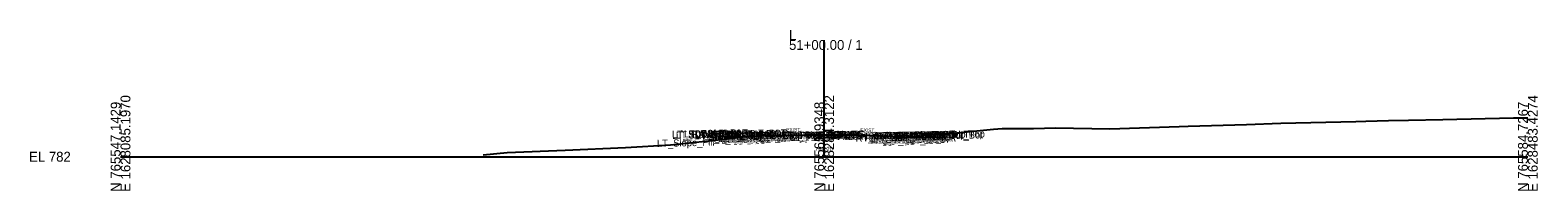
# Model space of a CAD drawing. Extents: x -26 to 4403, y -510 to 9556.
# Drawn here: x 3974.3 to 4402.8, y 990.3 to 1035.9 of the extents above; entities that cross this region are included whole.
import ezdxf

# ---------------------------------------------------------------- set-up
doc = ezdxf.new("R2010")
doc.units = 0
for name, color, linetype in [('Default', 7, 'Continuous'), ('Exist Cross Section Cell', 7, 'Continuous'), ('Exist XS Center Line Elevation Label', 7, 'Continuous'), ('Exist XS Ground Line', 7, 'Continuous'), ('Prop CMT Pvmt Course 1', 7, 'Continuous'), ('Prop XS SE Text', 7, 'Continuous'), ('Scratch_Level_0', 7, 'Continuous')]:
    doc.layers.add(name, color=color, linetype=linetype)

msp = doc.modelspace()

# ---------------------------------------------------------------- linework, layer by layer
at = {"layer": 'Exist Cross Section Cell'}
for p, q in [((4200, 1000), (4200, 1033.14)), ((4000, 1000), (4200, 1000)), ((4200, 1000), (4400, 1000))]:
    msp.add_line(p, q, dxfattribs=at)
at = {"layer": 'Exist XS Ground Line'}
msp.add_lwpolyline([(4103.02, 1000.53), (4109.92, 1001.15), (4126.34, 1001.82), (4143.53, 1002.6), (4156.34, 1003.41), (4170.67, 1004.87), (4175.04, 1005.42), (4178.52, 1005.83), (4178.89, 1005.78), (4181.08, 1005.93), (4182.4, 1005.99), (4185.35, 1006.05), (4195.01, 1006.21), (4200, 1006.2), (4204.25, 1006.19), (4207.07, 1006.19), (4216.25, 1005.9), (4219.03, 1005.8), (4220.54, 1005.71), (4225.42, 1005.51), (4226.33, 1005.6), (4227.42, 1005.73), (4227.92, 1006.09), (4229.72, 1006.21), (4231.23, 1006.3), (4234.93, 1006.51), (4248.08, 1007.84), (4250.54, 1008), (4259.47, 1007.99), (4265.74, 1008.23), (4281.22, 1007.92), (4300.92, 1008.6), (4303.46, 1008.65), (4320.01, 1009.13), (4329.77, 1009.51), (4351.1, 1010.04), (4353.96, 1010.09), (4360.43, 1010.31), (4366.12, 1010.38), (4375.84, 1010.57), (4395.9, 1011), (4400, 1011.05)], dxfattribs=at)
at = {"layer": 'Prop CMT Pvmt Course 1'}
for points in [[(4200, 1006.01), (4200, 1006.26)], [(4200, 1006.01), (4200, 1006.26)], [(4200, 1006.13), (4200, 1006.01), (4200, 1006.01)], [(4200, 1006.13), (4200, 1006.01), (4200, 1006.01)]]:
    msp.add_lwpolyline(points, dxfattribs=at)

# ---------------------------------------------------------------- texts
at = {"layer": 'Default'}
msp.add_text('-', height=0.0001, dxfattribs=at).set_placement((4000, 1000))
at = {"layer": 'Exist Cross Section Cell'}
for s, p in [('51+00.00 / 1', (4190, 1030.34)), ('L', (4190, 1033.14)), ('EL 782', (3974, 998.6))]:
    msp.add_text(s, height=2.8, dxfattribs=at).set_placement(p)
for s, p in [('E 1628085.1970', (4002.8, 990)), ('E 1628284.3122', (4202.8, 990)), ('E 1628483.4274', (4402.8, 990)), ('N 765547.1429', (4000, 990)), ('N 765565.9348', (4200, 990)), ('N 765584.7267', (4400, 990))]:
    msp.add_text(s, height=2.8, rotation=90, dxfattribs=at).set_placement(p)
at = {"layer": 'Exist XS Center Line Elevation Label'}
msp.add_text('788.20', height=1.2, dxfattribs=at).set_placement((4197.42, 1001.6))
at = {"layer": 'Prop XS SE Text'}
for rotation, p in [(0.5729, (4189.22, 1007.15)), (358.8542, (4210.27, 1007.05))]:
    msp.add_text('EXIST.', height=1, rotation=rotation, dxfattribs=at).set_placement(p)
at = {"layer": 'Scratch_Level_0'}
for s, p in [('LT_SDWK_Out_Top', (4156.76, 1005.39)), ('LT_SDWK_Out_Bot', (4156.79, 1005.06)), ('LT_Sub_Trench_Out_DLT', (4157.86, 1005.14)), ('LT_CSLP_Pnt', (4160.2, 1005.47)), ('LT_SDWK_In_Top', (4163.38, 1005.33)), ('LT_SDWK_In_Bot', (4163.41, 1005)), ('51+00.00', (4165.28, 1005.52)), ('LT_PV_Sub_Tie_Out', (4166.98, 1004.67)), ('LT_CG_Top_Face', (4167.28, 1005.23)), ('LT_CG_Top_BOC', (4167.8, 1005.25)), ('LT_CG_Top_Gut', (4168.26, 1004.74)), ('LT_PV_OEEOP_EG', (4169.57, 1004.73)), ('LT_PV1_OEEOP', (4171.9, 1004.75)), ('LT_PV1_OEOT', (4172.76, 1004.9)), ('RT_PV_IEEOP_EG', (4188.16, 1004.96)), ('LT_PV_IEEOP_EG', (4188.21, 1004.96)), ('RT_PV2_IEEOP', (4189.93, 1004.81)), ('LT_PV2_IEEOP', (4189.97, 1004.81)), ('RT_PV1_IEEOP', (4190.49, 1004.94)), ('LT_PV1_IEEOP', (4190.54, 1004.95)), ('PV2_PGL', (4193.93, 1004.89)), ('PV1_PGL', (4194.49, 1005.15)), ('51+00.00', (4208.18, 1004.85)), ('RT_Sub_Trench_Out_DLT', (4209.33, 1004.81)), ('RT_CG_Top_Face', (4213.27, 1004.9)), ('RT_CG_Top_BOC', (4214.79, 1004.92)), ('RT_SDWK_In_Top', (4217.33, 1004.99)), ('RT_CSLP_Pnt', (4220.15, 1005.03)), ('RT_Slope_Fill', (4220.5, 1005.04)), ('RT_SDWK_Out_Top', (4220.71, 1005.05)), ('RT_SDWK_Out_Bot', (4220.74, 1004.72)), ('51+00.00', (4222.89, 1005.09)), ('51+00.00', (4225.47, 1005.15)), ('LT_Slope_Fill', (4152.47, 1002.79)), ('LT_CG1_Shelf_Out', (4165.57, 1004.2)), ('LT_CG_Bot_BOC', (4167.84, 1004.24)), ('LT_Sub_OEOP', (4168.8, 1003.93)), ('LT_Sub_OEEOP', (4171.23, 1003.95)), ('LT_PV2_OEEOP', (4171.33, 1004.62)), ('LT_PV3_OEEOP', (4171.33, 1004.28)), ('LT_CG_Bot_IE', (4171.94, 1004.3)), ('LT_Sub_OEOT', (4172.1, 1003.96)), ('LT_PV2_OEOT', (4172.2, 1004.63)), ('LT_PV3_OEOT', (4172.2, 1004.3)), ('RT_PV3_IEEOP', (4189.93, 1004.48)), ('LT_PV3_IEEOP', (4189.97, 1004.48)), ('RT_PV_Sub_Tie_Out', (4208.94, 1004.27)), ('RT_PV_OEEOP_EG', (4211.55, 1004.32)), ('RT_Sub_OEEOP', (4213.22, 1003.65)), ('RT_PV2_OEEOP', (4213.32, 1004.31)), ('RT_PV3_OEEOP', (4213.32, 1003.98)), ('RT_CG1_Shelf_Out', (4213.56, 1003.87)), ('RT_PV1_OEEOP', (4213.88, 1004.45)), ('RT_CG_Bot_IE', (4213.92, 1003.99)), ('RT_Sub_OEOT', (4214.09, 1003.66)), ('RT_PV2_OEOT', (4214.18, 1004.33)), ('RT_PV3_OEOT', (4214.18, 1004)), ('RT_CG_Top_Gut', (4214.25, 1004.42)), ('RT_PV1_OEOT', (4214.75, 1004.59)), ('RT_CG_Bot_BOC', (4214.83, 1003.91)), ('RT_SDWK_In_Bot', (4217.37, 1004.65)), ('RT_Sub_OEOP', (4217.46, 1003.6))]:
    msp.add_text(s, height=2, rotation=1.1458, dxfattribs=at).set_placement(p)

doc.saveas('drawing.dxf')
